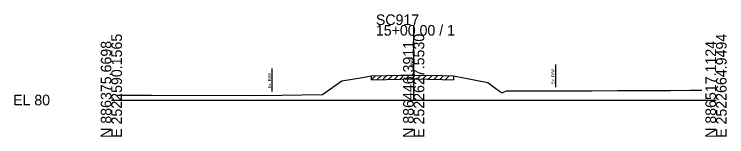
# Model space of a CAD drawing. Extents: x -26 to 218, y -10 to 12021.
# Drawn here: x -25.7 to 162.8, y 11490.3 to 11522.6 of the extents above; entities that cross this region are included whole.
import ezdxf

# ---------------------------------------------------------------- set-up
doc = ezdxf.new("R2010")
doc.units = 0
for name, color, linetype in [('RD_GPK_XS_Cell', 7, 'Continuous'), ('RD_XS_ExGround', 7, 'Continuous'), ('RD_XS_ExPaveRet', 7, 'Continuous'), ('RD_XS_ExRW', 7, 'Continuous'), ('RD_XS_TX_Elev_EX', 7, 'Continuous')]:
    doc.layers.add(name, color=color, linetype=linetype)

msp = doc.modelspace()

# ---------------------------------------------------------------- linework, layer by layer
at = {"layer": 'RD_GPK_XS_Cell'}
for p, q in [((80, 11500), (80, 11519.8)), ((0, 11500), (80, 11500)), ((80, 11500), (160, 11500))]:
    msp.add_line(p, q, dxfattribs=at)
at = {"layer": 'RD_XS_ExGround'}
for p, q in [((66.43, 11505.94), (68.88, 11506.35)), ((68.88, 11506.35), (76.62, 11506.53)), ((76.62, 11506.53), (79.93, 11506.6)), ((79.93, 11506.6), (87.56, 11506.43)), ((87.56, 11506.43), (90.52, 11506.37)), ((90.52, 11506.37), (93.26, 11505.82)), ((59.21, 11503.83), (60.99, 11505.06)), ((60.99, 11505.06), (66.43, 11505.94)), ((93.26, 11505.82), (99.64, 11504.58)), ((99.64, 11504.58), (102.12, 11502.81)), ((55.87, 11501.46), (59.21, 11503.83)), ((102.12, 11502.81), (103.39, 11501.92)), ((103.79, 11502.06), (104.59, 11502.38)), ((104.59, 11502.38), (127.13, 11502.46)), ((127.13, 11502.46), (133.95, 11502.48)), ((133.95, 11502.48), (147.96, 11502.53)), ((147.96, 11502.53), (153.19, 11502.59)), ((153.19, 11502.59), (154.16, 11502.6)), ((154.16, 11502.6), (156.26, 11502.62)), ((1.65, 11501.25), (10.63, 11501.26)), ((10.63, 11501.26), (37.53, 11501.22)), ((37.53, 11501.22), (45.08, 11501.32)), ((45.08, 11501.32), (55.87, 11501.46)), ((103.39, 11501.92), (103.79, 11502.06))]:
    msp.add_line(p, q, dxfattribs=at)
at = {"layer": 'RD_XS_ExPaveRet'}
for p, q in [((68.88, 11505.35), (69.9, 11506.38)), ((68.88, 11505.35), (68.88, 11506.35)), ((70.38, 11505.39), (71.4, 11506.41)), ((71.88, 11505.42), (72.9, 11506.44)), ((73.38, 11505.46), (74.4, 11506.48)), ((74.88, 11505.49), (75.9, 11506.51)), ((76.38, 11505.52), (77.4, 11506.55)), ((77.88, 11505.56), (78.9, 11506.58)), ((79.38, 11505.59), (80.38, 11506.59)), ((80.88, 11505.58), (81.86, 11506.56)), ((82.38, 11505.55), (83.36, 11506.52)), ((83.88, 11505.51), (84.86, 11506.49)), ((85.38, 11505.48), (86.36, 11506.46)), ((86.88, 11505.45), (87.86, 11506.43)), ((88.38, 11505.42), (89.36, 11506.4)), ((90.52, 11506.37), (90.52, 11505.37)), ((68.88, 11505.35), (76.62, 11505.53)), ((76.62, 11505.53), (79.93, 11505.6)), ((79.93, 11505.6), (87.56, 11505.43)), ((87.56, 11505.43), (90.52, 11505.37))]:
    msp.add_line(p, q, dxfattribs=at)
at = {"layer": 'RD_XS_ExRW'}
for p, q in [((42.5, 11508.29), (42.5, 11502.29)), ((117.5, 11509.42), (117.5, 11503.42)), ((117.5, 11509.42), (117.5, 11503.42))]:
    msp.add_line(p, q, dxfattribs=at)

# ---------------------------------------------------------------- texts
at = {"layer": 'RD_GPK_XS_Cell'}
for s, p in [('SC917', (70, 11519.8)), ('15+00.00 / 1', (70, 11517)), ('EL 80', (-26, 11498.6))]:
    msp.add_text(s, height=2.8, dxfattribs=at).set_placement(p)
for s, p in [('E 2522590.1565', (2.8, 11490)), ('E 2522627.5530', (82.8, 11490)), ('E 2522664.9494', (162.8, 11490)), ('N 886375.6698', (0, 11490)), ('N 886446.3911', (80, 11490)), ('N 886517.1124', (160, 11490))]:
    msp.add_text(s, height=2.8, rotation=90, dxfattribs=at).set_placement(p)
at = {"layer": 'RD_XS_ExRW'}
for p in [(117.25, 11504.21), (117.25, 11504.21), (42.25, 11503.07)]:
    msp.add_text('Ex. R/W ', height=0.8, rotation=90, dxfattribs=at).set_placement(p)
at = {"layer": 'RD_XS_TX_Elev_EX'}
msp.add_text('86.60', height=0.8, rotation=90, dxfattribs=at).set_placement((79.9, 11508.6))

doc.saveas('drawing.dxf')
